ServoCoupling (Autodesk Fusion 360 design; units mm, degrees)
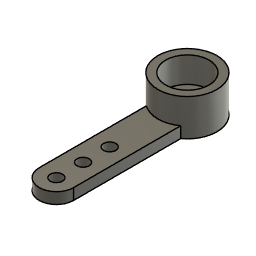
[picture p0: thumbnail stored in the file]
sketch "Esquisse1" plane through (0, 0, 0) normal (0, 1, 0) x axis (1, 0, 0)
  line L1 (-1.55, -11.8) -> (-1.55, -2.1494)
  line L2 (1.55, -11.8) -> (-1.55, -11.8)
  line L3 (1.55, -2.1494) -> (1.55, -11.8)
  line L4 (0, -22.5) -> (0, -1.75)
  line L5 (3.5, -13.35) -> (-2.4577, -13.35)
  line L6 (5, 2.65) -> (-3.4492, 2.65)
  circle C1 centre (0, 0) radius 2.65
  arc A1 centre (0, -11.8) radius 1.55 clockwise from (1.55, -11.8) to (-1.55, -11.8)
  circle C2 centre (0, -11.8) radius 0.55
  circle C3 centre (0, -9.4) radius 0.55
  circle C4 centre (0, -7) radius 0.55
  circle C5 centre (0, 0) radius 0.9
  point P1 (0, 0)
  point P2 (0, 0)
  point P3 (-1.55, -2.1494)
  point P6 (1.55, -2.1494)
  point P17 (0, 0)
  coincident P1 P2
  coincident C1 P3
  vertical L1
  perpendicular L1 L2
  coincident C1 P6
  perpendicular L2 L3
  tangent L1 A1
  perpendicular L4 L5
  horizontal L6
  tangent C1 L6
  tangent A1 L5
  concentric A1 C2
  coincident P1 P17
  dimension "d1" diameter C1 = 5.3
  dimension "d2" distance L1 L3 = 3.1
  dimension "d3" distance L1 L4 = 1.55 (= "d2 / 2")
  dimension "d4" distance L5 L6 = 16
  dimension "d5" diameter C2 = 1.1
  dimension "d12" diameter C5 = 1.8
  dimension "d8" R-Pattern1-uDistance = 2.4
  dimension "d9" R-Pattern1-vDistance = 0
extrude "Extrusion1" new body sketch "Esquisse1" profile of C1 L1 L3 A1 L4 C2 C3 C4 C5 along normal blind 1
sketch "Esquisse2" plane through (0, 1, 0) normal (0, 1, 0) x axis (-1, 0, 0)
  line L1 (-1.55, 2.1494) -> (-1.55, 11.8)
  line L2 (1.55, 11.8) -> (1.55, 2.1494)
  circle C1 centre (0, 11.8) radius 0.55
  circle C2 centre (0, 7) radius 0.55
  circle C3 centre (0, 9.4) radius 0.55
  circle C4 centre (0, 0) radius 0.9
  arc A1 centre (0, 11.8) radius 1.55 clockwise from (-1.55, 11.8) to (1.55, 11.8)
  arc A2 centre (0, 0) radius 2.65 clockwise from (1.55, 2.1494) to (-1.55, 2.1494)
  circle C5 centre (0, 0) radius 2.65
  circle C6 centre (0, 0) radius 1.95
  concentric C4 C5
  dimension "d13" = -0.7
extrude "Extrusion2" add sketch "Esquisse2" profile of A2 C5 C6 along normal blind 2.3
